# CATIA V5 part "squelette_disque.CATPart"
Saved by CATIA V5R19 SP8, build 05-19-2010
Part number: squelette_disque
Publications: "Plan.1", "Droite.1", "Droite.2"
Bounding box of the stored display mesh (mm): x 0 to 0, y -28 to 0, z -27.23 to 11.23
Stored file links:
  C:\Users\ThinkMotion\Desktop\EU_thinkMotion\iao\IAO_MMS_Groupe3\pmayet\pmayet_avant_optimisation\pmayet_avant_optimisation\squelette_disque.CATPart
  C:\Users\ThinkMotion\Desktop\EU_thinkMotion\iao\IAO_MMS_Groupe3\pmayet\pmayet_avant_optimisation\pmayet_avant_optimisation\squelette.CATProduct
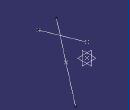
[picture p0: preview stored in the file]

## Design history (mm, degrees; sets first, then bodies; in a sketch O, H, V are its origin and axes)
Set1
  Point1 "PointA": linked copy from another document
  Point2 "Point2": linked copy from another document
  Point3 "Pointa": linked copy from another document
  Point4 "Point3": linked copy from another document
Set2
  Plane1: type OffsetPt, RefPlane yz-plane, RefPoint Point1
  Line1: type PtPt, FirstPoint Point2, SecondPoint Point3
  Line2: type Angle, RefPoint Point4, Curve Line1, Start -20, End 20, Angle 90
Body1 (main body)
